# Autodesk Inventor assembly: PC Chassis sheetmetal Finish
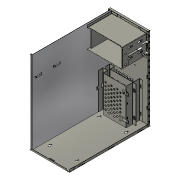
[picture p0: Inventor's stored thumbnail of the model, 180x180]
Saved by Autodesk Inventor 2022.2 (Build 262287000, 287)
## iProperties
Company: Autodesk Inc.
Created: 2006-09
Part Number: PC Chassis sheetmetal Finish
Document SubType Name: Assembly
Designer: Autodesk Inc.
Mass: 1117.78 g
Surface Area: 13233.4 cm^2
Volume: 1117.78 cm^3
Density: 1 g/cm^3
Author: Autodesk Inc.
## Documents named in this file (7)
- D:\Inventor\Tutorial 2\第8回 シートメタルとネスティング\PC Chassis\PC Chassis sheetmetal Finish.iam
- D:\Inventor\Tutorial 2\第8回 シートメタルとネスティング\PC Chassis\Bottom Bracket.ipt
- D:\Inventor\Tutorial 2\第8回 シートメタルとネスティング\PC Chassis\Front Bracket.ipt
- D:\Inventor\Tutorial 2\第8回 シートメタルとネスティング\PC Chassis\CDROM Bracket 01.ipt
- D:\Inventor\Tutorial 2\第8回 シートメタルとネスティング\PC Chassis\CDROM Bracket 02.ipt
- D:\Inventor\Tutorial 2\第8回 シートメタルとネスティング\PC Chassis\Hard Drive Bracket.ipt
- D:\Inventor\Tutorial 2\第8回 シートメタルとネスティング\PC Chassis\back support Finish.ipt
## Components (7 placed, 6 different names)
1. Bottom Bracket:1 — Mate:2, Mate:49, Mate:52, Mate:56, フラッシュ:7
2. Front Bracket:2 — Mate:2, Mate:41, Flush:5, Mate:42, Flush:6, Mate:56, フラッシュ:8, フラッシュ:9
3. CDROM Bracket 01:2 — Mate:42, Flush:6
4. CDROM Bracket 02:1 — Mate:41, Flush:5
5. Hard Drive Bracket:1 — Mate:51, Mate:52
6. Hard Drive Bracket:2 — Mate:49, Mate:51
7. back support Finish:1 — フラッシュ:7, フラッシュ:8, フラッシュ:9
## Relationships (12: Mate 7, Flush 5)
- Mate:2: Bottom Bracket:1 ↔ Front Bracket:2
- Mate:41: Front Bracket:2 ↔ CDROM Bracket 02:1
- Flush:5: Front Bracket:2 ↔ CDROM Bracket 02:1
- Mate:42: Front Bracket:2 ↔ CDROM Bracket 01:2
- Flush:6: Front Bracket:2 ↔ CDROM Bracket 01:2
- Mate:49: Bottom Bracket:1 ↔ Hard Drive Bracket:2
- Mate:51: Hard Drive Bracket:1 ↔ Hard Drive Bracket:2
- Mate:52: Bottom Bracket:1 ↔ Hard Drive Bracket:1
- Mate:56: Bottom Bracket:1 ↔ Front Bracket:2
- フラッシュ:7 [Flush]: Bottom Bracket:1 ↔ back support Finish:1
- フラッシュ:8 [Flush]: Front Bracket:2 ↔ back support Finish:1
- フラッシュ:9 [Flush]: Front Bracket:2 ↔ back support Finish:1
